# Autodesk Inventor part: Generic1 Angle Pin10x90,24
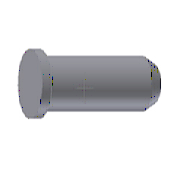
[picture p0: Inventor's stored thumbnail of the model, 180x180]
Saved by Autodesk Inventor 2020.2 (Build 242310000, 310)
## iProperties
Manager: www.cadconsulting.pl
Company: Fabian Stasiak CAD Consulting
Created: 2014-02
Part Number: Generic1 Angle Pin10x90,24
Material: DIN 1.0401
Description: Guide Pillar
Document SubType Name: Modeling
Designer: F.Stasiak
Standard Revision: 1
Manufacturer: Generic
Language: pl-PL
Size Designation: 10x90,24
Categories: <MemberInstance><Categories><Category DisplayName="Forma wtryskowa" InternalName="349578f2-f4d4-4954-8c09-8e99297a61c0" Mnemonic="MOLD"><Category DisplayName="K
Mass: 1.9988 g
Surface Area: 11.4076 cm^2
Volume: 1.9988 cm^3
Density: 7.82 g/cm^3
Appearance: Canary
Catalog Web Link: www.expertbooks.pl
IsCustomPart: 1
Author: F.Stasiak
Subject: Zbiór ćwiczeń. Autodesk Inventor 2020. Kurs Professional
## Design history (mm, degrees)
sketch "Sketch1"
  geometry: L1 (0, -67.093)-(0, 17.015) reference; L2 (0, 5)-(-7, 5); L3 (-7, 5)-(-7, 0); L4 (-7, 0)-(-4.5, 0); L5 (-4.5, 0)-(-4.5, -1); L6 (-4.5, -1)-(-5, -1); L7 (-5, -1)-(-5, -81.24); L8 (-5, -81.24)-(-3.813, -84.895); L9 (-3.337, -85.24)-(0, -85.24); L10 (0, 5)-(0, -85.24); A1 r 0.5 centre (-3.337, -84.74) between (-3.813, -84.895) and (-3.337, -85.24); 3 further points
  constraints: 18 end point, 4 parallel, 4 point on line, 3 perpendicular, 2 point on circle, 2 tangent, 1 centre point, 1 collinear, 1 horizontal alignment, 1 midpoint
  dimensions: "d0" = 90.24 distance between parallel lines of L9 L2 (= AP_l); "d2" = 4 distance from line of L9 L7.end (= AP_l1); "d3" = 10 diameter of L7 L1 (= AP_d1); "d4" = 14 diameter of L3 L1 (= AP_d2); "d5" = 5 distance between parallel lines of L2 L4 (= AP_k); "d6" = 1 distance between parallel lines of L4 L6 (= AP_REF2); "d9" = 9 diameter of L5 L1 (= AP_d1 - AP_REF2); "d10" = 0.5 radius of A1 (= AP_REF1); "d15" = 18 deg angle of L7 L8 (= AP_REF4)
revolve "Revolution1" sketch "Sketch1" stored, may be unused: angle "d11" = 90 deg
fillet "Fillet1" dims "d42" = 0.3 (= AP_REF3)
node "AP_PP"
  workaxis "Work Axis1"
feature "Stitch Surface3" dims "d54" = 0.254 (derived)
feature "Rzeźbienie2"
body "Solid1"
sketch "Sketch2"
  geometry: C1 r 5 at (0, 0) reference; 1 further point
body "Srf1"
body "Srf3"
sketch "Sketch3"
  geometry: C1 r 7 at (0, 0) reference; C2 r 7 at (0, 0); 1 further point
  constraints: 1 centre point, 1 coincident, 1 concentric
body "Srf2"
body "Srf4"
workplane "Work Plane1"
body "Srf5"
body "Srf6"
extrude_surface "ExtrusionSrf1" dims "d22" = 85.24 (= AP_l - AP_k), "d23" = 0
patch "Boundary Patch1" dims "d30" = 0, "d43" = 0
extrude_surface "ExtrusionSrf2" dims "d34" = 15 (= 3 x AP_k), "d35" = 0
patch "Boundary Patch2" dims "d38" = 0, "d47" = 0, "d48" = 0
patch "Boundary Patch3" dims "d52" = 0, "d53" = 0
other parameters: "AP_d1" = 10 [user parameter; used in 2 equation terms], "AP_l" = 90.24 [user parameter; used in 2 equation terms], "AP_d2" = 14 [user parameter; used in 1 equation term], "AP_k" = 5 [user parameter; used in 3 equation terms], "AP_l1" = 4 [user parameter; used in 1 equation term], "AP_ang" = 18 deg [user parameter; used in 1 equation term], "AP_REF1" = 0.5 [user parameter; used in 1 equation term], "AP_REF2" = 1 [user parameter; used in 2 equation terms], "AP_REF3" = 0.3 [user parameter; used in 1 equation term], "d44" = 0, "d45" = 18 deg (= AP_ang), "AP_REF4" = 18 deg [user parameter; used in 1 equation term]
